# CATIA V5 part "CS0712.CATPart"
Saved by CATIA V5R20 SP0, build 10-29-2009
Part number: CS0712
Revision: 7
Definition: design
Nomenclature: CS0712
Source: made
Description: NOT SPECIFIED
Bounding box of the stored display mesh (mm): x -11.818 to 12, y -12 to 12, z -22 to 6
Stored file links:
  C:\Users\Raffaele\Desktop\3D X SITO CF\BOLEX\20-TILTED COLUMN SUPPORT\CS0712.CATPart
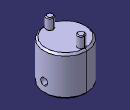
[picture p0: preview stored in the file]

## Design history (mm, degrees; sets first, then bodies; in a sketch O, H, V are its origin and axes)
Body1 "MANIFOLD_SOLID_BREP #683" (main body)
  Solid1: solid without history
